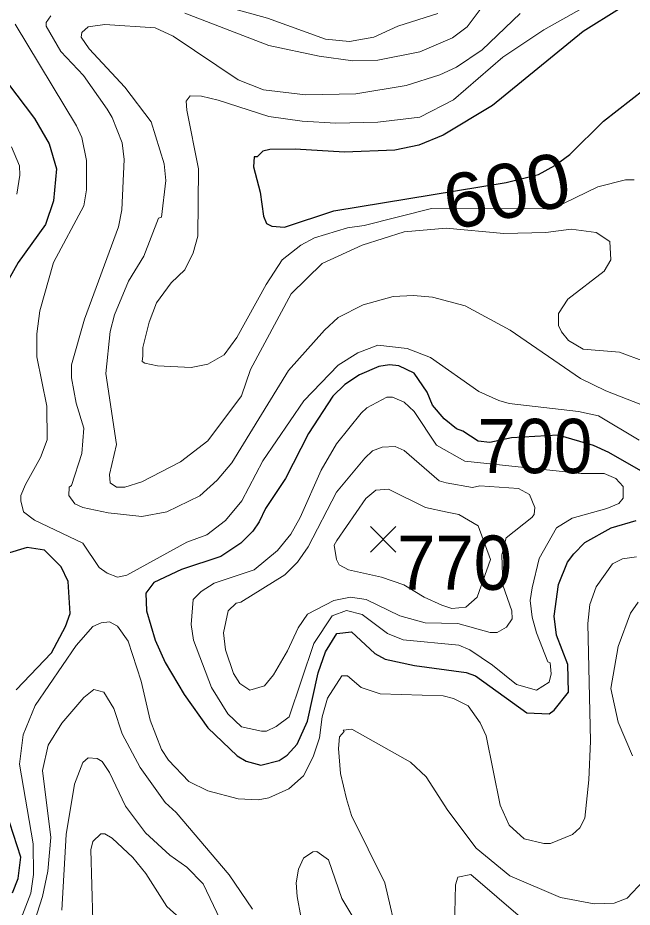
# Model space of a CAD drawing. Extents: x 423 to 448.8, y 7456.3 to 7484.
# Drawn here: x 428.618 to 429.524, y 7458.637 to 7459.948 of the extents above; entities that cross this region are included whole.
import ezdxf
from ezdxf.enums import TextEntityAlignment as Align

# ---------------------------------------------------------------- set-up
doc = ezdxf.new("R2010")
doc.units = 0
doc.header["$LTSCALE"] = 0.032
for name, color, linetype, lineweight in [('1', 7, 'Continuous', 25), ('2', 7, 'Continuous', 13), ('21', 7, 'Continuous', 25)]:
    doc.layers.add(name, color=color, linetype=linetype, lineweight=lineweight)
doc.layers.add('61', color=7, linetype='Continuous')

msp = doc.modelspace()

# ---------------------------------------------------------------- linework, layer by layer
at = {"layer": '1'}
for points in [[(429.5049, 7459.9606), (429.4515, 7459.9274), (429.3177, 7459.8183), (429.245, 7459.7743), (429.2094, 7459.7596), (429.1738, 7459.7526), (429.0996, 7459.7495), (429.0269, 7459.7541), (428.9897, 7459.7534), (428.9796, 7459.7511), (428.9712, 7459.7425), (428.9665, 7459.7425), (428.9657, 7459.7279), (428.9758, 7459.6907), (428.9804, 7459.6552), (428.9851, 7459.6443), (428.9928, 7459.6404), (429.0114, 7459.6389), (429.0841, 7459.6629), (429.3379, 7459.705), (429.3858, 7459.7167), (429.4098, 7459.7297), (429.4317, 7459.7462), (429.4816, 7459.7951), (429.542, 7459.8423)], [(428.5628, 7459.9042), (428.6432, 7459.799), (428.6649, 7459.7619), (428.6757, 7459.7248), (428.671, 7459.6776), (428.6594, 7459.6427), (428.6192, 7459.5871), (428.5983, 7459.55)], [(429.5745, 7459.2584), (429.4894, 7459.3071), (429.4669, 7459.3171), (429.4148, 7459.3326), (429.3461, 7459.3285), (429.3139, 7459.3218), (429.2969, 7459.3236), (429.2741, 7459.3382), (429.265, 7459.3419), (429.2465, 7459.3566), (429.2295, 7459.3767), (429.2217, 7459.396), (429.2024, 7459.4239), (429.18, 7459.4347), (429.1661, 7459.4362), (429.1506, 7459.4339), (429.122, 7459.4216), (429.1003, 7459.4069), (429.0825, 7459.3898), (429.0469, 7459.3349), (429.0129, 7459.2684), (428.9835, 7459.2243), (428.9742, 7459.205), (428.965, 7459.191), (428.9472, 7459.1732), (428.9178, 7459.1539), (428.8598, 7459.1346), (428.8188, 7459.1153), (428.8072, 7459.0998), (428.8079, 7459.0735), (428.8211, 7459.0302), (428.8358, 7458.9977), (428.8636, 7458.9505), (428.8984, 7458.901), (428.9418, 7458.86), (428.9549, 7458.8523), (428.9765, 7458.8461), (429.0036, 7458.853), (429.0152, 7458.8608), (429.0299, 7458.877), (429.0454, 7458.9111), (429.0609, 7458.9822), (429.0717, 7459.0132), (429.0887, 7459.0402), (429.1103, 7459.0426), (429.1444, 7459.0108), (429.1599, 7459.0023), (429.2032, 7458.993), (429.279, 7458.983), (429.2929, 7458.9776), (429.3687, 7458.9234), (429.4012, 7458.9219), (429.4089, 7458.9273), (429.4298, 7458.9536), (429.429, 7458.9946), (429.412, 7459.0379), (429.4089, 7459.0658), (429.4151, 7459.1122), (429.4282, 7459.1454), (429.4375, 7459.1574), (429.4538, 7459.1741), (429.4925, 7459.1957), (429.5296, 7459.2065)], [(428.6161, 7458.9574), (428.6679, 7459.0116), (428.6888, 7459.0503), (428.6958, 7459.0696), (428.6927, 7459.1168), (428.6826, 7459.1385), (428.6579, 7459.1632), (428.6324, 7459.1671), (428.6014, 7459.1578)], [(428.6107, 7458.6581), (428.6192, 7458.679), (428.6231, 7458.7107), (428.5844, 7458.8276)]]:
    msp.add_lwpolyline(points, dxfattribs=at)
at = {"layer": '2'}
for points in [[(429.4538, 7459.9637), (429.3935, 7459.9297), (429.3331, 7459.8895), (429.2604, 7459.8268), (429.2109, 7459.8013), (429.1491, 7459.7936), (429.0872, 7459.792), (429.0377, 7459.7951), (428.9882, 7459.8021), (428.9139, 7459.8261), (428.8892, 7459.8322), (428.8722, 7459.8323), (428.8667, 7459.8245), (428.8675, 7459.8114), (428.8845, 7459.7248), (428.8837, 7459.6258), (428.8768, 7459.601), (428.8644, 7459.5763), (428.8443, 7459.5569), (428.8226, 7459.5275), (428.8118, 7459.4989), (428.8025, 7459.4618), (428.8025, 7459.4494), (428.8017, 7459.4409), (428.8056, 7459.4385), (428.8242, 7459.4347), (428.8737, 7459.4324), (428.8985, 7459.437), (428.9224, 7459.4509), (428.941, 7459.4765), (428.9843, 7459.5546), (429.0082, 7459.5909), (429.0353, 7459.6126), (429.0554, 7459.6234)], [(429.2372, 7459.9537), (429.1785, 7459.9351), (429.1429, 7459.9189), (429.1073, 7459.9127), (429.0717, 7459.9158), (428.9866, 7459.9467), (428.9062, 7459.9692)], [(429.5365, 7459.3775), (429.4847, 7459.3976), (429.4476, 7459.4161), (429.3439, 7459.4873), (429.2775, 7459.5229), (429.2295, 7459.536), (429.2017, 7459.5383), (429.1715, 7459.5368), (429.1274, 7459.5244), (429.0903, 7459.5058), (429.0702, 7459.4873), (429.0175, 7459.4278), (428.934, 7459.2916), (428.9124, 7459.2661), (428.8868, 7459.2429), (428.8381, 7459.2197), (428.801, 7459.2127), (428.7515, 7459.2181), (428.7144, 7459.2259), (428.7027, 7459.2313), (428.6935, 7459.2437), (428.6942, 7459.256), (428.6974, 7459.2583), (428.7128, 7459.3055), (428.7159, 7459.3427), (428.7043, 7459.3798), (428.6974, 7459.4169), (428.6974, 7459.4362), (428.7167, 7459.5036), (428.767, 7459.6397), (428.7716, 7459.6644), (428.7754, 7459.7387), (428.7724, 7459.7634), (428.7577, 7459.8006), (428.7499, 7459.8129), (428.7151, 7459.8624), (428.6818, 7459.898), (428.6602, 7459.9351), (428.6602, 7459.9405), (428.6672, 7459.9506)], [(429.542, 7459.4409), (429.5049, 7459.4548), (429.4515, 7459.4594), (429.4298, 7459.4718), (429.4198, 7459.4849), (429.4151, 7459.4943), (429.4151, 7459.512), (429.429, 7459.5329), (429.4824, 7459.5739), (429.4924, 7459.5909), (429.4909, 7459.618), (429.4708, 7459.6311), (429.4337, 7459.6358), (429.3966, 7459.6311), (429.3347, 7459.6296), (429.2496, 7459.6373), (429.1877, 7459.6319), (429.1259, 7459.6126), (429.0671, 7459.5855), (429.0214, 7459.5407), (428.9611, 7459.4293), (428.948, 7459.3906), (428.8985, 7459.3241), (428.8582, 7459.2931), (428.801, 7459.2638), (428.7763, 7459.256), (428.7638, 7459.256), (428.7546, 7459.2622), (428.7538, 7459.2746), (428.7639, 7459.3187), (428.7484, 7459.4231), (428.7546, 7459.485), (428.7608, 7459.5097), (428.7816, 7459.5592), (428.8041, 7459.5964), (428.8257, 7459.6521), (428.8304, 7459.6536), (428.8365, 7459.7077), (428.8342, 7459.7325), (428.8149, 7459.7944), (428.7762, 7459.8454), (428.7236, 7459.9019), (428.712, 7459.9189), (428.7128, 7459.9258), (428.7221, 7459.9343), (428.7469, 7459.9375), (428.8211, 7459.9328), (428.8474, 7459.9204), (428.9433, 7459.8562), (428.9804, 7459.8415), (429.0423, 7459.8338), (429.1166, 7459.8353), (429.1908, 7459.8477), (429.2403, 7459.8632), (429.2651, 7459.8748), (429.3029, 7459.9003), (429.3586, 7459.9537)], [(428.8644, 7459.9545), (428.9882, 7459.9065), (429.0624, 7459.891), (429.1119, 7459.8841), (429.1491, 7459.8849), (429.2109, 7459.8972), (429.2589, 7459.9181), (429.2805, 7459.9344), (429.2999, 7459.9599)], [(428.6146, 7459.9382), (428.7051, 7459.7882), (428.7128, 7459.7712), (428.7198, 7459.7371), (428.7198, 7459.6938), (428.7159, 7459.6706), (428.671, 7459.5871), (428.6509, 7459.5159), (428.6463, 7459.4819), (428.6463, 7459.4479), (428.661, 7459.3752)], [(428.6091, 7459.7573), (428.6208, 7459.7294), (428.6216, 7459.7155), (428.6169, 7459.6876)], [(429.0554, 7459.6234), (429.1042, 7459.6381), (429.1289, 7459.6412), (429.228, 7459.6667), (429.4063, 7459.6661), (429.4731, 7459.6984), (429.5141, 7459.7085), (429.5265, 7459.7085)], [(428.661, 7459.3752), (428.6618, 7459.3257), (428.6517, 7459.2994), (428.63, 7459.2599), (428.6231, 7459.2437), (428.6231, 7459.2359), (428.627, 7459.2197), (428.6432, 7459.2073), (428.7144, 7459.1733), (428.7383, 7459.1377), (428.75, 7459.1292), (428.7654, 7459.123), (428.7793, 7459.1261), (428.8675, 7459.1748), (428.8969, 7459.1856), (428.9247, 7459.2065), (428.9487, 7459.2359), (428.9796, 7459.2947), (429.04, 7459.3829), (429.0903, 7459.4355), (429.1197, 7459.454), (429.1491, 7459.4649), (429.1924, 7459.4602), (429.2264, 7459.4471), (429.2976, 7459.3968), (429.327, 7459.3836), (429.3424, 7459.379), (429.4445, 7459.3674), (429.4739, 7459.3612), (429.5342, 7459.3249)], [(429.5303, 7459.1531), (429.5095, 7459.1501), (429.4948, 7459.1431), (429.4708, 7459.1091), (429.4615, 7459.0828), (429.4584, 7459.0549), (429.4623, 7458.8817), (429.46, 7458.8245), (429.4538, 7458.768), (429.4468, 7458.754), (429.436, 7458.744), (429.4035, 7458.7308), (429.3935, 7458.7308), (429.3648, 7458.7378), (429.3424, 7458.7579), (429.3292, 7458.7873), (429.3084, 7458.8894), (429.2999, 7458.9087), (429.282, 7458.9335), (429.2604, 7458.9443), (429.245, 7458.9482), (429.1522, 7458.9513), (429.1243, 7458.9605), (429.1042, 7458.9776), (429.0957, 7458.9776), (429.0748, 7458.9451), (429.0671, 7458.9173), (429.0632, 7458.8863), (429.0539, 7458.8585), (429.0392, 7458.8306), (429.0176, 7458.8113), (428.9882, 7458.7982), (428.9727, 7458.7951), (428.9433, 7458.7966), (428.8985, 7458.8082), (428.8706, 7458.8221), (428.8404, 7458.8538), (428.8304, 7458.8693), (428.8134, 7458.9126), (428.8002, 7458.9699), (428.7809, 7459.0287), (428.7654, 7459.0511), (428.7538, 7459.0573), (428.7414, 7459.0557), (428.729, 7459.0503), (428.7043, 7459.0225), (428.644, 7458.9343), (428.6262, 7458.891), (428.6208, 7458.8477), (428.6409, 7458.7301), (428.6417, 7458.6852)], [(429.5242, 7458.86), (429.5033, 7458.9095), (429.4924, 7458.959), (429.5033, 7459.0209), (429.5211, 7459.0704), (429.5326, 7459.0866)], [(428.6432, 7458.6156), (428.6548, 7458.6527), (428.6625, 7458.6899), (428.6672, 7458.7394), (428.6548, 7458.8384), (428.6633, 7458.8755), (428.6834, 7458.908), (428.7159, 7458.9459), (428.7306, 7458.9575), (428.7453, 7458.9536), (428.76, 7458.9296), (428.7724, 7458.8925), (428.7986, 7458.843), (428.8358, 7458.7912), (428.852, 7458.7765), (428.9301, 7458.6844), (428.9642, 7458.6341)], [(429.1792, 7458.5862), (429.1591, 7458.6729), (429.1103, 7458.7719), (429.1026, 7458.7966), (429.0941, 7458.8337), (429.091, 7458.8709), (429.0926, 7458.8879), (429.0995, 7458.8956), (429.098, 7458.8979), (429.1104, 7458.8995), (429.197, 7458.8507), (429.2202, 7458.8291), (429.2519, 7458.7796), (429.2937, 7458.7239), (429.3432, 7458.6829), (429.4182, 7458.6512), (429.4677, 7458.6419), (429.4971, 7458.6427), (429.5164, 7458.6504), (429.5404, 7458.6759)], [(428.6834, 7458.6326), (428.6896, 7458.744), (428.702, 7458.8183), (428.7144, 7458.85), (428.7221, 7458.8569), (428.7352, 7458.8561), (428.743, 7458.8515), (428.7538, 7458.8353), (428.777, 7458.7858), (428.8064, 7458.7463), (428.8427, 7458.7138), (428.8675, 7458.6961), (428.8915, 7458.6713), (428.927, 7458.5971)], [(428.8907, 7458.5909), (428.8381, 7458.638), (428.8071, 7458.6868), (428.7878, 7458.71), (428.7577, 7458.7386), (428.7469, 7458.7448), (428.7407, 7458.7448), (428.729, 7458.7339), (428.7259, 7458.7216), (428.729, 7458.6172)], [(429.0353, 7458.6234), (429.0299, 7458.6527), (429.0284, 7458.6729), (429.0322, 7458.693), (429.0392, 7458.7092), (429.0532, 7458.7185), (429.0593, 7458.7192), (429.0763, 7458.7068), (429.0957, 7458.6497), (429.115, 7458.6179)], [(428.6417, 7458.6852), (428.6378, 7458.6574), (428.6254, 7458.6256), (428.5929, 7458.5885)], [(429.262, 7458.6079), (429.2635, 7458.6698), (429.2666, 7458.6813), (429.2859, 7458.6852), (429.3625, 7458.6195)]]:
    msp.add_lwpolyline(points, dxfattribs=at)
for points in [[(429.3764, 7459.1075), (429.3865, 7459.1509), (429.412, 7459.1957), (429.4352, 7459.2104), (429.4863, 7459.2243), (429.5041, 7459.232), (429.5102, 7459.2398), (429.5102, 7459.2568), (429.4994, 7459.2684), (429.4824, 7459.2762), (429.4484, 7459.2762), (429.2772, 7459.2943), (429.2356, 7459.3179), (429.2024, 7459.3674), (429.1877, 7459.3813), (429.1707, 7459.3883), (429.1622, 7459.3883), (429.1328, 7459.3728), (429.1243, 7459.3651), (429.0879, 7459.3195), (429.0655, 7459.2808), (429.0346, 7459.2112), (429.0206, 7459.1864), (429.0013, 7459.1624), (428.9665, 7459.1338), (428.9077, 7459.1145), (428.8884, 7459.1021), (428.8768, 7459.0905), (428.8737, 7459.0534), (428.8775, 7459.0302), (428.9038, 7458.9606), (428.9278, 7458.9219), (428.9479, 7458.9026), (428.9774, 7458.8964), (428.9851, 7458.8964), (428.999, 7458.9033), (429.0183, 7458.9173), (429.0547, 7459.0256), (429.0817, 7459.0665), (429.1027, 7459.0743), (429.1259, 7459.0681), (429.163, 7459.0402), (429.1862, 7459.0309), (429.2682, 7459.0232), (429.2844, 7459.0162), (429.3177, 7458.9938), (429.3533, 7458.9652), (429.3826, 7458.9567), (429.4012, 7458.9683), (429.4043, 7458.9807), (429.4027, 7458.9969), (429.3996, 7458.9985), (429.3826, 7459.041), (429.3765, 7459.0642), (429.3734, 7459.089)], [(429.0121, 7459.1268), (429.0307, 7459.1454), (429.0462, 7459.1679), (429.0879, 7459.2483), (429.1297, 7459.2986), (429.1413, 7459.3094), (429.1552, 7459.3148), (429.1746, 7459.3156), (429.1877, 7459.3101), (429.2395, 7459.2653), (429.2496, 7459.2622), (429.2883, 7459.2552), (429.2991, 7459.2576), (429.3563, 7459.2537), (429.3726, 7459.2452), (429.3803, 7459.2259), (429.3795, 7459.2158), (429.3757, 7459.2112), (429.3378, 7459.181), (429.3318, 7459.1563), (429.3333, 7459.1113), (429.3463, 7459.0735), (429.3471, 7459.0619), (429.3385, 7459.0495), (429.3246, 7459.0418), (429.3146, 7459.0418), (429.2666, 7459.0549), (429.2187, 7459.0557), (429.1815, 7459.0665), (429.132, 7459.0905), (429.1088, 7459.0936), (429.0841, 7459.089), (429.0454, 7459.0689), (429.0315, 7459.0488), (429.016, 7459.0147), (428.9951, 7458.9791), (428.982, 7458.9629), (428.9603, 7458.9567), (428.9456, 7458.9667), (428.9363, 7458.9814), (428.9247, 7459.0163), (428.9217, 7459.041), (428.9286, 7459.0735), (428.9402, 7459.0851), (428.9472, 7459.0866)], [(429.2512, 7459.2189), (429.2682, 7459.2158), (429.2968, 7459.1988), (429.3148, 7459.1494), (429.2953, 7459.0938), (429.2788, 7459.0788), (429.2578, 7459.0773), (429.2434, 7459.082), (429.2171, 7459.0936), (429.1874, 7459.1119), (429.1544, 7459.123), (429.1057, 7459.1338), (429.0918, 7459.1415), (429.0879, 7459.1493), (429.0848, 7459.1702), (429.0887, 7459.1772), (429.1313, 7459.239), (429.1459, 7459.2514), (429.1645, 7459.2529), (429.2194, 7459.2259)]]:
    msp.add_lwpolyline(points, close=True, dxfattribs=at)
at = {"layer": '21'}
for p, q in [((429.1382, 7459.1978), (429.1757, 7459.1603)), ((429.1757, 7459.1978), (429.1382, 7459.1603))]:
    msp.add_line(p, q, dxfattribs=at)

# ---------------------------------------------------------------- texts
at = {"layer": '61', "width": 1.05}
msp.add_text('600', height=0.08, rotation=12.08, dxfattribs=at).set_placement((429.347, 7459.6534), align=Align.CENTER)
at = {"layer": '61', "width": 0.95}
for s, p in [('700', (429.3803, 7459.2765)), ('770', (429.262, 7459.1046))]:
    msp.add_text(s, height=0.08, dxfattribs=at).set_placement(p, align=Align.CENTER)

doc.saveas('drawing.dxf')
